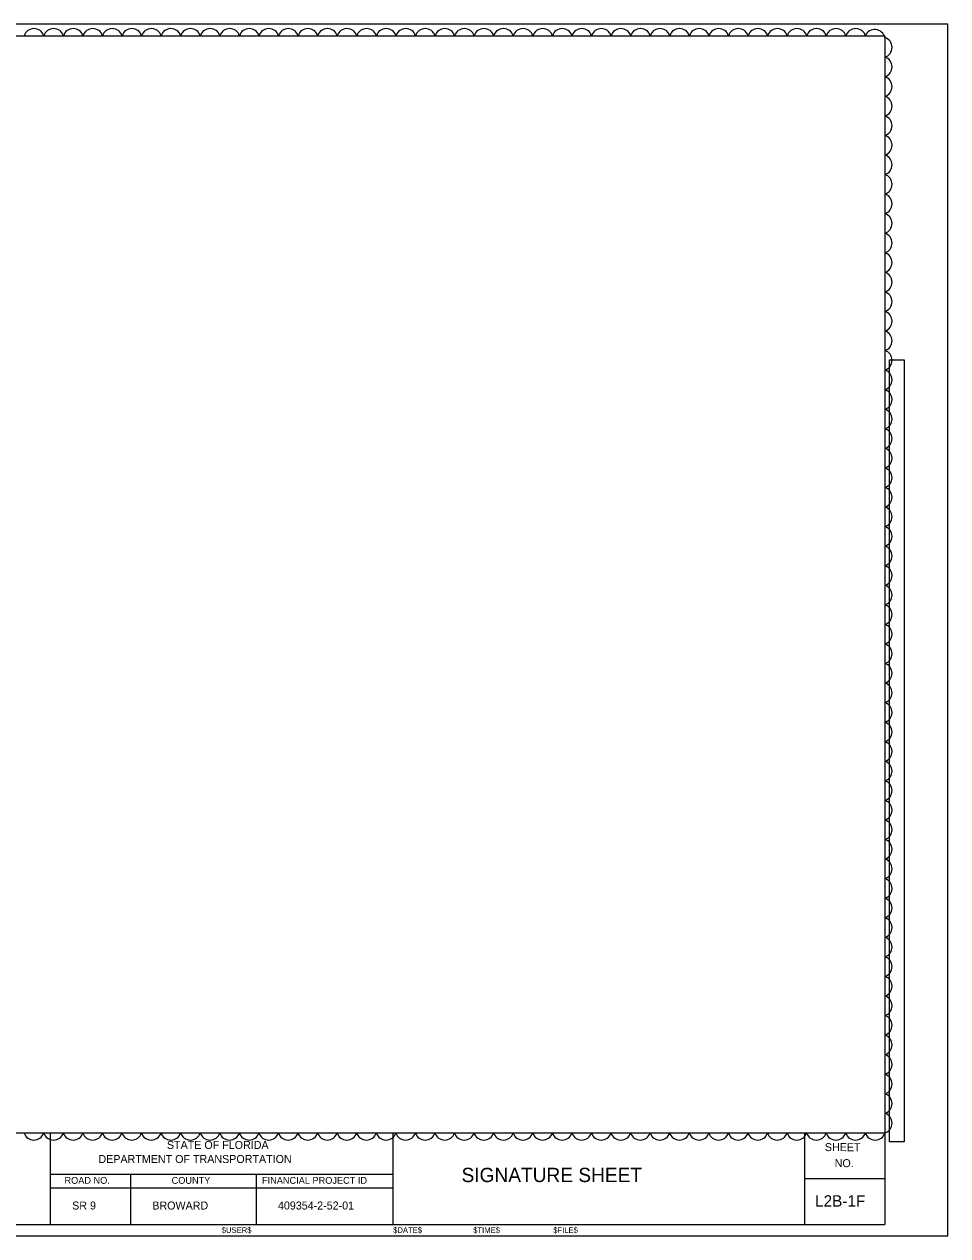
# Model space of a CAD drawing. Extents: x -816.9 to -790.1, y -2199.5 to -2188.9.
# Drawn here: x -802.91 to -794.84, y -2199.5 to -2188.9 of the extents above; entities that cross this region are included whole.
import ezdxf

# ---------------------------------------------------------------- set-up
doc = ezdxf.new("R2010")
doc.units = 0
for name, color, linetype in [('Cloud_dp', 7, 'Continuous'), ('PlotBorder_dp', 7, 'Continuous'), ('ScratchEle_dp', 7, 'Continuous'), ('SheetBorder_dp', 7, 'Continuous'), ('SheetLines_dp', 7, 'Continuous'), ('TextMinor', 7, 'Continuous'), ('TextMisc', 7, 'Continuous'), ('TextShtNo', 7, 'Continuous')]:
    doc.layers.add(name, color=color, linetype=linetype)

msp = doc.modelspace()

# ---------------------------------------------------------------- linework, layer by layer
at = {"layer": 'Cloud_dp'}
for centre, radius, start, end in [((-802.829, -2189.028), 0.0897, 17.5, 162.5), ((-802.657, -2189.028), 0.0897, 17.5, 162.5), ((-802.486, -2189.028), 0.0897, 17.5, 162.5), ((-802.315, -2189.028), 0.0897, 17.5, 162.5), ((-802.144, -2189.028), 0.0897, 17.5, 162.5), ((-801.973, -2189.028), 0.0897, 17.5, 162.5), ((-801.802, -2189.028), 0.0897, 17.5, 162.5), ((-801.631, -2189.028), 0.0897, 17.5, 162.5), ((-801.46, -2189.028), 0.0897, 17.5, 162.5), ((-801.288, -2189.028), 0.0897, 17.5, 162.5), ((-801.117, -2189.028), 0.0897, 17.5, 162.5), ((-800.946, -2189.028), 0.0897, 17.5, 162.5), ((-800.775, -2189.028), 0.0897, 17.5, 162.5), ((-800.604, -2189.028), 0.0897, 17.5, 162.5), ((-800.433, -2189.028), 0.0897, 17.5, 162.5), ((-800.262, -2189.028), 0.0897, 17.5, 162.5), ((-800.091, -2189.028), 0.0897, 17.5, 162.5), ((-799.919, -2189.028), 0.0897, 17.5, 162.5), ((-799.748, -2189.028), 0.0897, 17.5, 162.5), ((-799.577, -2189.028), 0.0897, 17.5, 162.5), ((-799.406, -2189.028), 0.0897, 17.5, 162.5), ((-799.235, -2189.028), 0.0897, 17.5, 162.5), ((-799.064, -2189.028), 0.0897, 17.5, 162.5), ((-798.893, -2189.028), 0.0897, 17.5, 162.5), ((-798.722, -2189.028), 0.0897, 17.5, 162.5), ((-798.551, -2189.028), 0.0897, 17.5, 162.5), ((-798.379, -2189.028), 0.0897, 17.5, 162.5), ((-798.208, -2189.028), 0.0897, 17.5, 162.5), ((-798.037, -2189.028), 0.0897, 17.5, 162.5), ((-797.866, -2189.028), 0.0897, 17.5, 162.5), ((-797.695, -2189.028), 0.0897, 17.5, 162.5), ((-797.524, -2189.028), 0.0897, 17.5, 162.5), ((-797.353, -2189.028), 0.0897, 17.5, 162.5), ((-797.182, -2189.028), 0.0897, 17.5, 162.5), ((-797.01, -2189.028), 0.0897, 17.5, 162.5), ((-796.839, -2189.028), 0.0897, 17.5, 162.5), ((-796.668, -2189.028), 0.0897, 17.5, 162.5), ((-796.497, -2189.028), 0.0897, 17.5, 162.5), ((-796.326, -2189.028), 0.0897, 17.5, 162.5), ((-796.155, -2189.028), 0.0897, 17.5, 162.5), ((-795.984, -2189.028), 0.0897, 17.5, 162.5), ((-795.813, -2189.028), 0.0897, 17.5, 162.5), ((-795.641, -2189.028), 0.0897, 17.5, 162.5), ((-795.474, -2189.036), 0.0896, 11.7454, 156.7454), ((-795.413, -2189.103), 0.0897, 287.5, 72.5), ((-795.413, -2189.274), 0.0897, 287.5, 72.5), ((-795.413, -2189.446), 0.0897, 287.5, 72.5), ((-795.413, -2189.617), 0.0897, 287.5, 72.5), ((-795.413, -2189.788), 0.0897, 287.5, 72.5), ((-795.413, -2189.959), 0.0897, 287.5, 72.5), ((-795.413, -2190.13), 0.0897, 287.5, 72.5), ((-795.413, -2190.301), 0.0897, 287.5, 72.5), ((-795.413, -2190.472), 0.0897, 287.5, 72.5), ((-795.413, -2190.643), 0.0897, 287.5, 72.5), ((-795.413, -2190.815), 0.0897, 287.5, 72.5), ((-795.413, -2190.986), 0.0897, 287.5, 72.5), ((-795.413, -2191.157), 0.0897, 287.5, 72.5), ((-795.413, -2191.328), 0.0897, 287.5, 72.5), ((-795.413, -2191.499), 0.0897, 287.5, 72.5), ((-795.413, -2191.67), 0.0897, 287.5, 72.5), ((-795.413, -2191.841), 0.0897, 287.5, 72.5), ((-795.413, -2192.012), 0.0897, 287.5, 72.5), ((-795.413, -2192.184), 0.0897, 287.5, 72.5), ((-795.413, -2192.355), 0.0897, 287.5, 72.5), ((-795.413, -2192.526), 0.0897, 287.5, 72.5), ((-795.413, -2192.697), 0.0897, 287.5, 72.5), ((-795.413, -2192.868), 0.0897, 287.5, 72.5), ((-795.413, -2193.039), 0.0897, 287.5, 72.5), ((-795.413, -2193.21), 0.0897, 287.5, 72.5), ((-795.413, -2193.381), 0.0897, 287.5, 72.5), ((-795.413, -2193.553), 0.0897, 287.5, 72.5), ((-795.413, -2193.724), 0.0897, 287.5, 72.5), ((-795.413, -2193.895), 0.0897, 287.5, 72.5), ((-795.413, -2194.066), 0.0897, 287.5, 72.5), ((-795.413, -2194.237), 0.0897, 287.5, 72.5), ((-795.413, -2194.408), 0.0897, 287.5, 72.5), ((-795.413, -2194.579), 0.0897, 287.5, 72.5), ((-795.413, -2194.75), 0.0897, 287.5, 72.5), ((-795.413, -2194.922), 0.0897, 287.5, 72.5), ((-795.413, -2195.093), 0.0897, 287.5, 72.5), ((-795.413, -2195.264), 0.0897, 287.5, 72.5), ((-795.413, -2195.435), 0.0897, 287.5, 72.5), ((-795.413, -2195.606), 0.0897, 287.5, 72.5), ((-795.413, -2195.777), 0.0897, 287.5, 72.5), ((-795.413, -2195.948), 0.0897, 287.5, 72.5), ((-795.413, -2196.119), 0.0897, 287.5, 72.5), ((-795.413, -2196.29), 0.0897, 287.5, 72.5), ((-795.413, -2196.462), 0.0897, 287.5, 72.5), ((-795.413, -2196.633), 0.0897, 287.5, 72.5), ((-795.413, -2196.804), 0.0897, 287.5, 72.5), ((-795.413, -2196.975), 0.0897, 287.5, 72.5), ((-795.413, -2197.146), 0.0897, 287.5, 72.5), ((-795.413, -2197.317), 0.0897, 287.5, 72.5), ((-795.413, -2197.488), 0.0897, 287.5, 72.5), ((-795.413, -2197.659), 0.0897, 287.5, 72.5), ((-795.413, -2197.831), 0.0897, 287.5, 72.5), ((-795.413, -2198.002), 0.0897, 287.5, 72.5), ((-795.413, -2198.173), 0.0897, 287.5, 72.5), ((-795.413, -2198.344), 0.0897, 287.5, 72.5), ((-795.413, -2198.515), 0.0897, 287.5, 72.5), ((-802.83, -2198.574), 0.0897, 197.5, 342.5), ((-802.658, -2198.574), 0.0897, 197.5, 342.5), ((-802.487, -2198.574), 0.0897, 197.5, 342.5), ((-802.316, -2198.574), 0.0897, 197.5, 342.5), ((-802.145, -2198.574), 0.0897, 197.5, 342.5), ((-801.974, -2198.574), 0.0897, 197.5, 342.5), ((-801.803, -2198.574), 0.0897, 197.5, 342.5), ((-801.632, -2198.574), 0.0897, 197.5, 342.5), ((-801.461, -2198.574), 0.0897, 197.5, 342.5), ((-801.289, -2198.574), 0.0897, 197.5, 342.5), ((-801.118, -2198.574), 0.0897, 197.5, 342.5), ((-800.947, -2198.574), 0.0897, 197.5, 342.5), ((-800.776, -2198.574), 0.0897, 197.5, 342.5), ((-800.605, -2198.574), 0.0897, 197.5, 342.5), ((-800.434, -2198.574), 0.0897, 197.5, 342.5), ((-800.263, -2198.574), 0.0897, 197.5, 342.5), ((-800.092, -2198.574), 0.0897, 197.5, 342.5), ((-799.921, -2198.574), 0.0897, 197.5, 342.5), ((-799.749, -2198.574), 0.0897, 197.5, 342.5), ((-799.578, -2198.574), 0.0897, 197.5, 342.5), ((-799.407, -2198.574), 0.0897, 197.5, 342.5), ((-799.236, -2198.574), 0.0897, 197.5, 342.5), ((-799.065, -2198.574), 0.0897, 197.5, 342.5), ((-798.894, -2198.574), 0.0897, 197.5, 342.5), ((-798.723, -2198.574), 0.0897, 197.5, 342.5), ((-798.552, -2198.574), 0.0897, 197.5, 342.5), ((-798.38, -2198.574), 0.0897, 197.5, 342.5), ((-798.209, -2198.574), 0.0897, 197.5, 342.5), ((-798.038, -2198.574), 0.0897, 197.5, 342.5), ((-797.867, -2198.574), 0.0897, 197.5, 342.5), ((-797.696, -2198.574), 0.0897, 197.5, 342.5), ((-797.525, -2198.574), 0.0897, 197.5, 342.5), ((-797.354, -2198.574), 0.0897, 197.5, 342.5), ((-797.183, -2198.574), 0.0897, 197.5, 342.5), ((-797.011, -2198.574), 0.0897, 197.5, 342.5), ((-796.84, -2198.574), 0.0897, 197.5, 342.5), ((-796.669, -2198.574), 0.0897, 197.5, 342.5), ((-796.498, -2198.574), 0.0897, 197.5, 342.5), ((-796.327, -2198.574), 0.0897, 197.5, 342.5), ((-796.156, -2198.574), 0.0897, 197.5, 342.5), ((-795.985, -2198.574), 0.0897, 197.5, 342.5), ((-795.814, -2198.574), 0.0897, 197.5, 342.5), ((-795.642, -2198.574), 0.0897, 197.5, 342.5), ((-795.471, -2198.574), 0.0897, 197.5, 342.5)]:
    msp.add_arc(centre, radius, start, end, dxfattribs=at)
at = {"layer": 'PlotBorder_dp'}
msp.add_lwpolyline([(-811.336, -2199.501), (-794.836, -2199.501), (-794.836, -2188.901), (-811.336, -2188.901)], close=True, dxfattribs=at)
at = {"layer": 'ScratchEle_dp'}
msp.add_lwpolyline([(-795.346, -2191.838), (-795.218, -2191.838), (-795.218, -2198.68), (-795.346, -2198.68)], close=True, dxfattribs=at)
at = {"layer": 'SheetBorder_dp'}
for p, q in [((-810.786, -2189.001), (-795.386, -2189.001)), ((-795.386, -2189.001), (-795.386, -2199.401)), ((-810.786, -2198.601), (-795.386, -2198.601)), ((-810.786, -2199.401), (-795.386, -2199.401))]:
    msp.add_line(p, q, dxfattribs=at)
at = {"layer": 'SheetLines_dp'}
for p, q in [((-802.686, -2198.601), (-802.686, -2199.401)), ((-799.686, -2199.401), (-799.686, -2198.601)), ((-796.086, -2199.401), (-796.086, -2198.601)), ((-802.686, -2198.961), (-799.686, -2198.961)), ((-801.986, -2198.961), (-801.986, -2199.401)), ((-800.886, -2198.961), (-800.886, -2199.401)), ((-796.086, -2199.001), (-795.386, -2199.001)), ((-802.686, -2199.081), (-799.686, -2199.081))]:
    msp.add_line(p, q, dxfattribs=at)

# ---------------------------------------------------------------- texts
at = {"layer": 'TextMinor'}
msp.add_text('$USER$', height=0.05, dxfattribs=at).set_placement((-801.187, -2199.476))
for s, p in [('$DATE$', (-799.687, -2199.476)), ('$TIME$', (-798.987, -2199.476)), ('$FILE$', (-798.287, -2199.476))]:
    msp.add_text(s, height=0.05, rotation=360, dxfattribs=at).set_placement(p)
at = {"layer": 'TextMisc'}
for s, height, p in [('STATE OF FLORIDA', 0.07, (-801.666, -2198.741)), ('DEPARTMENT OF TRANSPORTATION', 0.07, (-802.265, -2198.864)), ('       SIGNATURE SHEET         ', 0.125, (-799.414, -2199.031)), ('ROAD NO.', 0.06, (-802.562, -2199.046)), ('COUNTY', 0.06, (-801.625, -2199.046)), ('FINANCIAL PROJECT ID', 0.06, (-800.834, -2199.046)), (' SR 9  ', 0.07, (-802.521, -2199.271)), ('  BROWARD   ', 0.07, (-801.846, -2199.271)), ('409354-2-52-01', 0.07, (-800.695, -2199.271))]:
    msp.add_text(s, height=height, dxfattribs=at).set_placement(p)
for s, p in [('SHEET', (-795.911, -2198.76)), ('NO.', (-795.825, -2198.9))]:
    msp.add_text(s, height=0.07, rotation=359.8607, dxfattribs=at).set_placement(p)
at = {"layer": 'TextShtNo'}
msp.add_text('L2B-1F', height=0.1, dxfattribs=at).set_placement((-795.996, -2199.246))

doc.saveas('drawing.dxf')
